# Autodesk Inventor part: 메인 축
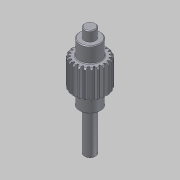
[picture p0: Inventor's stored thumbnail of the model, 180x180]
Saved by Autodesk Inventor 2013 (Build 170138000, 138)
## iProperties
Created: 2013-12
Part Number: 메인 축
Material: 강
Document SubType Name: Modeling
Designer: 한국산업디자인학원
Categories: <?xml version="1.0" encoding="UTF-16"?> <MemberInstance><Categories><FamilyTemplate><FamilyTemplateParameter ValueType="xs:double" Id="1" ObjectReferenceKey="da
Density: 1 g/cm^3
CustomPartVersion: 1
Author: 한국산업디자인학원
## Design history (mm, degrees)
sketch "Sketch1"
  geometry: C1 r 12 at (0, 0)
  constraints: 1 centre point
  dimensions: "d0" = 24 diameter of C1 (= da_da)
extrude "Extrusion1" new body sketch "Sketch1" distance "d1" = 20 (= da_b); taper "d2" = 0 deg
workplane "Work Plane2"
feature "피치 지름" dims "d4" = 10, "d5" = 0
workplane "Work Plane8"
workplane "Work Plane9"
chamfer "모따기1" distance "d49" = 1; stored, may be unused: second distance "d50" = 2, angle "d51" = 45 deg
sketch "스케치3"
  geometry: C1 r 7.5 at (0, 0); 1 further point
  constraints: 1 centre point, 1 coincident
  dimensions: "d52" = 15 diameter of C1
extrude "돌출2" join sketch "스케치3" distance "d53" = 11; taper "d54" = 0 deg
sketch "스케치4"
  geometry: C1 r 4 at (0, 0); 1 further point
  constraints: 1 centre point, 1 coincident
  dimensions: "d55" = 8 diameter of C1
extrude "돌출3" join sketch "스케치4" distance "d56" = 7; taper "d57" = 0 deg
sketch "스케치5"
  geometry: C1 r 7.5 at (0, 0) reference; C2 r 7.5 at (0, 0) reference; 1 further point
extrude "돌출4" join sketch "스케치5" distance "d62" = 11; taper "d63" = 0 deg
sketch "스케치6"
  geometry: C1 r 4 at (0, 0); 1 further point
  constraints: 1 centre point, 1 coincident
  dimensions: "d64" = 8 diameter of C1
extrude "돌출5" join sketch "스케치6" distance "d65" = 30; taper "d66" = 0 deg
chamfer "모따기2" distance "d58" = 0.5; stored, may be unused: second distance "d59" = 2, angle "d60" = 45 deg
fillet "모깎기1" dims "d61" = 0.5
feature "스퍼 기어" dims "da_b" = 20, "da_d" = 22, "da_aw" = 31, "da_da" = 24, "da_df" = 19.5, "da_dw" = 22, angle "da_beta" = 0 deg, "da_lefttooth" = 0, "da_righttooth" = 0
body "Solid1"
sketch "Sketch2"
  geometry: C1 r 12 at (0, 0) reference; C2 r 11 at (0, 0)
  constraints: 1 centre point, 1 coincident
  dimensions: "d3" = 22 diameter of C2 (= da_dw)
body "Srf1"
node "투영된 루프1"
other parameters: "d16" = 31 (= da_aw), "d17" = 0, "d34" = 1.428 (computed from da_z), "d39" = 0, "d41" = 0, "d43" = 31 (= da_aw), "d46" = 31 (= da_aw), "d47" = 0, "d48" = 0
